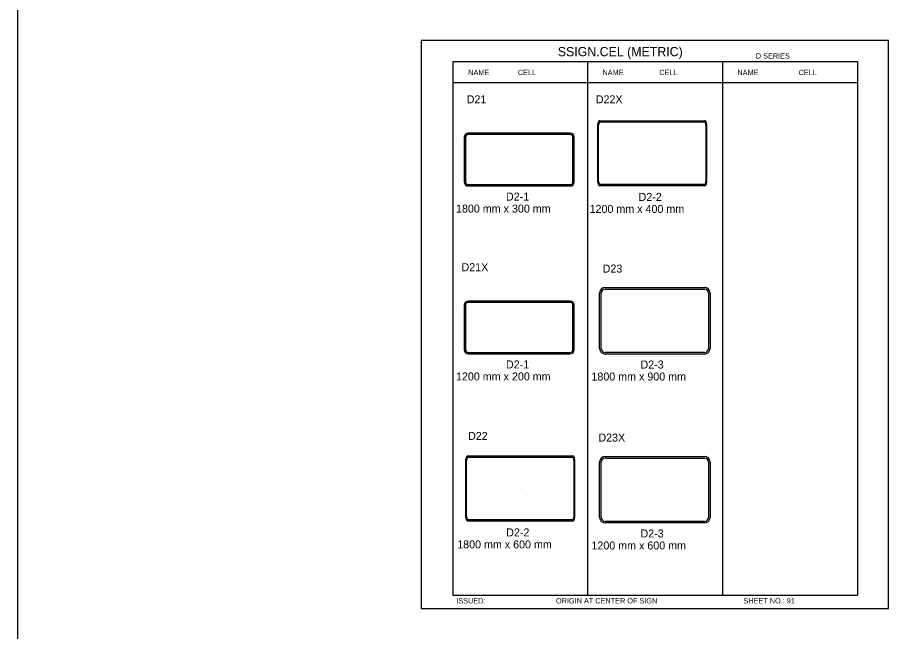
# Model space of a CAD drawing. Extents: x -12 to 6962, y -3756 to 679.
# Drawn here: x 4034.4 to 4360.9, y -13.7 to 216.7 of the extents above; entities that cross this region are included whole.
import ezdxf

# ---------------------------------------------------------------- set-up
doc = ezdxf.new("R2010")
doc.units = 0
for name, color, linetype in [('Level 1', 7, 'Continuous'), ('Level 2', 7, 'Continuous'), ('Level 3', 7, 'Continuous'), ('Level 61', 7, 'Continuous')]:
    doc.layers.add(name, color=color, linetype=linetype)

msp = doc.modelspace()

# ---------------------------------------------------------------- linework, layer by layer
at = {"layer": 'Level 1'}
for p, q in [((4349.26, 200), (4197.5, 200)), ((4197.5, 200), (4197.5, 0)), ((4248.09, 200), (4248.09, 0)), ((4298.67, 200), (4298.67, 0)), ((4349.26, 200), (4349.26, 0)), ((4349.26, 192.08), (4197.5, 192.08)), ((4251.95, 154.77), (4251.95, 176.72)), ((4252.2, 155.13), (4252.2, 176.36)), ((4252.63, 177.94), (4291.98, 177.94)), ((4252.83, 177.48), (4291.78, 177.48)), ((4292.41, 176.36), (4292.41, 155.13)), ((4292.66, 176.72), (4292.66, 154.77)), ((4241.57, 173.26), (4203.36, 173.26)), ((4201.86, 171.76), (4201.86, 154.95)), ((4202.36, 171.76), (4202.36, 154.95)), ((4241.57, 172.76), (4203.36, 172.76)), ((4242.57, 154.95), (4242.57, 171.76)), ((4243.07, 154.95), (4243.07, 171.76)), ((4223.24, 163.35), (4223.24, 163.35)), ((4272.3, 165.75), (4272.3, 165.75)), ((4203.36, 153.95), (4241.57, 153.95)), ((4291.98, 153.55), (4252.63, 153.55)), ((4291.78, 154.01), (4252.83, 154.01)), ((4203.36, 153.45), (4241.57, 153.45)), ((4254.67, 115.38), (4291.88, 115.38)), ((4254.67, 114.78), (4291.88, 114.78)), ((4252.57, 92.52), (4252.57, 113.28)), ((4253.17, 92.52), (4253.17, 113.28)), ((4293.38, 113.28), (4293.38, 92.52)), ((4293.98, 113.28), (4293.98, 92.52)), ((4201.86, 108.8), (4201.86, 91.99)), ((4202.36, 108.8), (4202.36, 91.99)), ((4241.57, 110.3), (4203.36, 110.3)), ((4241.57, 109.8), (4203.36, 109.8)), ((4242.57, 91.99), (4242.57, 108.8)), ((4243.07, 91.99), (4243.07, 108.8)), ((4273.28, 102.75), (4273.28, 102.75)), ((4223.24, 100.39), (4223.24, 100.39)), ((4203.36, 90.99), (4241.57, 90.99)), ((4203.36, 90.49), (4241.57, 90.49)), ((4291.88, 91.02), (4254.67, 91.02)), ((4291.88, 90.42), (4254.67, 90.42)), ((4202.47, 29.02), (4202.47, 50.96)), ((4202.73, 29.38), (4202.73, 50.6)), ((4203.15, 52.18), (4242.5, 52.18)), ((4203.35, 51.73), (4242.3, 51.73)), ((4242.93, 50.6), (4242.93, 29.38)), ((4243.18, 50.96), (4243.18, 29.02)), ((4252.57, 29.15), (4252.57, 49.91)), ((4253.17, 29.15), (4253.17, 49.91)), ((4254.67, 52.01), (4291.88, 52.01)), ((4254.67, 51.41), (4291.88, 51.41)), ((4293.38, 49.91), (4293.38, 29.15)), ((4293.98, 49.91), (4293.98, 29.15)), ((4222.83, 39.99), (4222.83, 39.99)), ((4273.28, 39.39), (4273.28, 39.39)), ((4242.5, 27.8), (4203.15, 27.8)), ((4242.3, 28.25), (4203.35, 28.25)), ((4291.88, 27.65), (4254.67, 27.65)), ((4291.88, 27.05), (4254.67, 27.05)), ((4197.5, 0), (4349.26, 0))]:
    msp.add_line(p, q, dxfattribs=at)
for centre, radius, start, end in [((4203.36, 171.76), 1.5, 90, 180), ((4241.57, 171.76), 1.5, 0, 90), ((4203.36, 171.76), 1, 90, 180), ((4241.57, 171.76), 1, 0, 90), ((4203.36, 154.95), 1.5, 180, 270), ((4203.36, 154.95), 1, 180, 270), ((4241.57, 154.95), 1, 270, 0), ((4241.57, 154.95), 1.5, 270, 0), ((4254.67, 113.28), 2.1, 90, 180), ((4254.67, 113.28), 1.5, 90, 180), ((4291.88, 113.28), 2.1, 0, 90), ((4291.88, 113.28), 1.5, 0, 90), ((4203.36, 108.8), 1.5, 90, 180), ((4203.36, 108.8), 1, 90, 180), ((4241.57, 108.8), 1.5, 0, 90), ((4241.57, 108.8), 1, 0, 90), ((4203.36, 91.99), 1.5, 180, 270), ((4203.36, 91.99), 1, 180, 270), ((4241.57, 91.99), 1, 270, 0), ((4241.57, 91.99), 1.5, 270, 0), ((4254.67, 92.52), 2.1, 180, 270), ((4254.67, 92.52), 1.5, 180, 270), ((4291.88, 92.52), 1.5, 270, 0), ((4291.88, 92.52), 2.1, 270, 0), ((4254.67, 49.91), 2.1, 90, 180), ((4254.67, 49.91), 1.5, 90, 180), ((4291.88, 49.91), 2.1, 0, 90), ((4291.88, 49.91), 1.5, 0, 90), ((4254.67, 29.15), 2.1, 180, 270), ((4254.67, 29.15), 1.5, 180, 270), ((4291.88, 29.15), 1.5, 270, 0), ((4291.88, 29.15), 2.1, 270, 0)]:
    msp.add_arc(centre, radius, start, end, dxfattribs=at)
for centre, major_axis, start_param, end_param in [((4252.63, 176.72), (0, -1.22), 3.141593, 4.712389), ((4252.83, 176.36), (0, -1.13), 3.141593, 4.712389), ((4291.78, 176.36), (0, 1.13), 4.712389, 6.283185), ((4291.98, 176.72), (0, 1.22), 4.712389, 6.283185), ((4252.63, 154.77), (0, -1.22), 4.712389, 6.283185), ((4252.83, 155.13), (0, -1.13), 4.712389, 6.283185), ((4291.78, 155.13), (0, 1.13), 3.141593, 4.712389), ((4291.98, 154.77), (0, 1.22), 3.141593, 4.712389), ((4203.15, 50.96), (0, -1.22), 3.141593, 4.712389), ((4203.35, 50.6), (0, -1.13), 3.141593, 4.712389), ((4242.3, 50.6), (0, 1.13), 4.712389, 6.283185), ((4242.5, 50.96), (0, 1.22), 4.712389, 6.283185), ((4203.15, 29.02), (0, -1.22), 4.712389, 6.283185), ((4203.35, 29.38), (0, -1.13), 4.712389, 6.283185), ((4242.3, 29.38), (0, 1.13), 3.141593, 4.712389), ((4242.5, 29.02), (0, 1.22), 3.141593, 4.712389)]:
    msp.add_ellipse(centre, major_axis=major_axis, ratio=0.5565, start_param=start_param, end_param=end_param, dxfattribs=at)
at = {"layer": 'Level 3'}
msp.add_line((4034.35, 661.66), (4034.35, -1225.34), dxfattribs=at)
at = {"layer": 'Level 61'}
msp.add_lwpolyline([(4185.63, -5.05), (4360.89, -5.05), (4360.89, 208.05), (4185.63, 208.05)], close=True, dxfattribs=at)

# ---------------------------------------------------------------- texts
at = {"layer": 'Level 2'}
for s, p in [('D21', (4202.75, 184.46)), ('D22X', (4251.14, 184.46)), ('D21X', (4200.81, 121.5)), ('D23', (4253.71, 120.97)), ('D22', (4203.26, 58.21)), ('D23X', (4252.12, 57.6))]:
    msp.add_text(s, height=3, dxfattribs=at).set_placement(p)
at = {"layer": 'Level 3'}
for s, height, p in [('SSIGN.CEL (METRIC)', 3.4642, (4236.89, 202.11)), ('D SERIES', 1.979, (4311.13, 201.24)), ('NAME', 1.98, (4203.31, 195.04)), ('CELL', 1.98, (4221.94, 195.04)), ('NAME', 1.98, (4253.64, 195.04)), ('CELL', 1.98, (4274.96, 195.04)), ('NAME', 1.98, (4304.23, 195.04)), ('CELL', 1.98, (4327.16, 195.04)), ('D2-1', 3, (4217.47, 147.97)), ('D2-2', 3, (4267.19, 147.86)), ('1800 mm x 300 mm', 3, (4198.75, 143.47)), ('1200 mm x 400 mm', 3, (4248.82, 143.36)), ('D2-1', 3, (4217.47, 85.02)), ('D2-3', 3, (4267.89, 84.98)), ('1200 mm x 200 mm', 3, (4198.75, 80.52)), ('1800 mm x 900 mm', 3, (4249.51, 80.48)), ('D2-2', 3, (4217.58, 22.02)), ('D2-3', 3, (4267.89, 21.62)), ('1800 mm x 600 mm', 3, (4199.2, 17.52)), ('1200 mm x 600 mm', 3, (4249.51, 17.12)), ('ISSUED:', 1.98, (4198.85, -3.12)), ('ORIGIN AT CENTER OF SIGN', 1.9795, (4236.23, -3.12)), ('SHEET NO.: 91', 1.9795, (4306.49, -3.12))]:
    msp.add_text(s, height=height, dxfattribs=at).set_placement(p)

doc.saveas('drawing.dxf')
